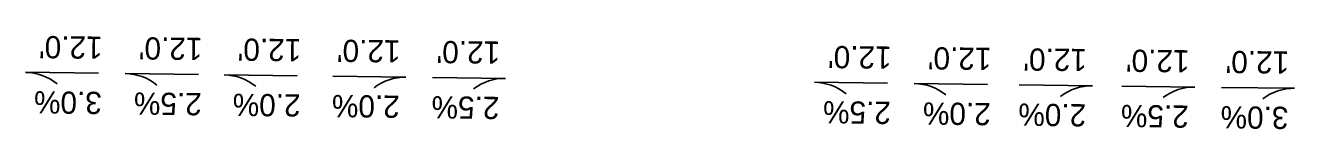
# Model space of a CAD drawing. Extents: x 20505303 to 20506906, y 7965397 to 7979025.
# Drawn here: x 20506343.7 to 20506495.7, y 7973802.7 to 7973813.9 of the extents above; entities that cross this region are included whole.
import ezdxf

# ---------------------------------------------------------------- set-up
doc = ezdxf.new("R2010")
doc.units = 0
doc.layers.add('Alignment', color=7, linetype='Continuous')

msp = doc.modelspace()

# ---------------------------------------------------------------- linework, layer by layer
at = {"layer": 'Alignment'}
for p, q in [((20506352.43, 7973809.42), (20506343.66, 7973809.54)), ((20506364.4, 7973809.27), (20506355.63, 7973809.38)), ((20506376.23, 7973809.13), (20506367.46, 7973809.24)), ((20506380.48, 7973809.07), (20506389.25, 7973808.96)), ((20506392.42, 7973808.92), (20506401.19, 7973808.81)), ((20506446.96, 7973808.24), (20506438.19, 7973808.35)), ((20506458.93, 7973808.08), (20506450.16, 7973808.2)), ((20506462.72, 7973808.04), (20506471.49, 7973807.93)), ((20506475.01, 7973807.88), (20506483.78, 7973807.77)), ((20506486.95, 7973807.73), (20506495.72, 7973807.62))]:
    msp.add_line(p, q, dxfattribs=at)
for centre, start, end in [((20506343.58, 7973803.37), 51.076, 89.2791), ((20506355.55, 7973803.22), 51.076, 89.2791), ((20506367.39, 7973803.07), 51.076, 89.2791), ((20506389.18, 7973802.8), 89.2791, 127.4821), ((20506401.11, 7973802.65), 89.2791, 127.4821), ((20506438.11, 7973802.18), 51.076, 89.2791), ((20506450.08, 7973802.03), 51.076, 89.2791), ((20506471.42, 7973801.76), 89.2791, 127.4821), ((20506483.71, 7973801.61), 89.2791, 127.4821), ((20506495.65, 7973801.46), 89.2791, 127.4821)]:
    msp.add_arc(centre, 6.16, start, end, dxfattribs=at)

# ---------------------------------------------------------------- texts
for s, p in [("12.0'", (20506352.92, 7973813.81)), ("12.0'", (20506364.88, 7973813.66)), ("12.0'", (20506376.72, 7973813.51)), ("12.0'", (20506388.61, 7973813.37)), ("12.0'", (20506400.55, 7973813.22)), ("12.0'", (20506447.45, 7973812.62)), ("12.0'", (20506459.41, 7973812.47)), ("12.0'", (20506470.85, 7973812.33)), ("12.0'", (20506483.14, 7973812.18)), ("12.0'", (20506495.08, 7973812.03)), ('3.0%', (20506352.83, 7973807.19)), ('2.5%', (20506364.8, 7973807.04)), ('2.0%', (20506376.64, 7973806.89)), ('2.0%', (20506388.52, 7973806.74)), ('2.5%', (20506400.46, 7973806.59)), ('2.5%', (20506447.36, 7973806)), ('2.0%', (20506459.33, 7973805.85)), ('2.0%', (20506470.76, 7973805.71)), ('2.5%', (20506483.05, 7973805.55)), ('3.0%', (20506494.99, 7973805.4))]:
    msp.add_text(s, height=2.664, rotation=179.3818, dxfattribs=at).set_placement(p)

doc.saveas('drawing.dxf')
